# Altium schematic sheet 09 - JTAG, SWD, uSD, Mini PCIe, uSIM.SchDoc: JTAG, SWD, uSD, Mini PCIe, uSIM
size A3; PageSetup: Record=PageOptions¦CenterHorizontal=True¦CenterVertical=True¦PrintScale=0.70¦XCorrection=1.00¦YCorrection=1.00¦PrintKind=0¦BorderSize=5000000¦LeftOffset=0¦BottomOffset=0¦Orientation=2¦PaperLength=4200¦PaperWidth=2970¦Scale=100¦PaperSource=7¦PrintQuality=600¦MediaType=1¦DitherType=10¦PaperKind=A4¦PrintScaleMode=1; Author: Juan Anzola; SheetNumber: 9; SheetTotal: 21
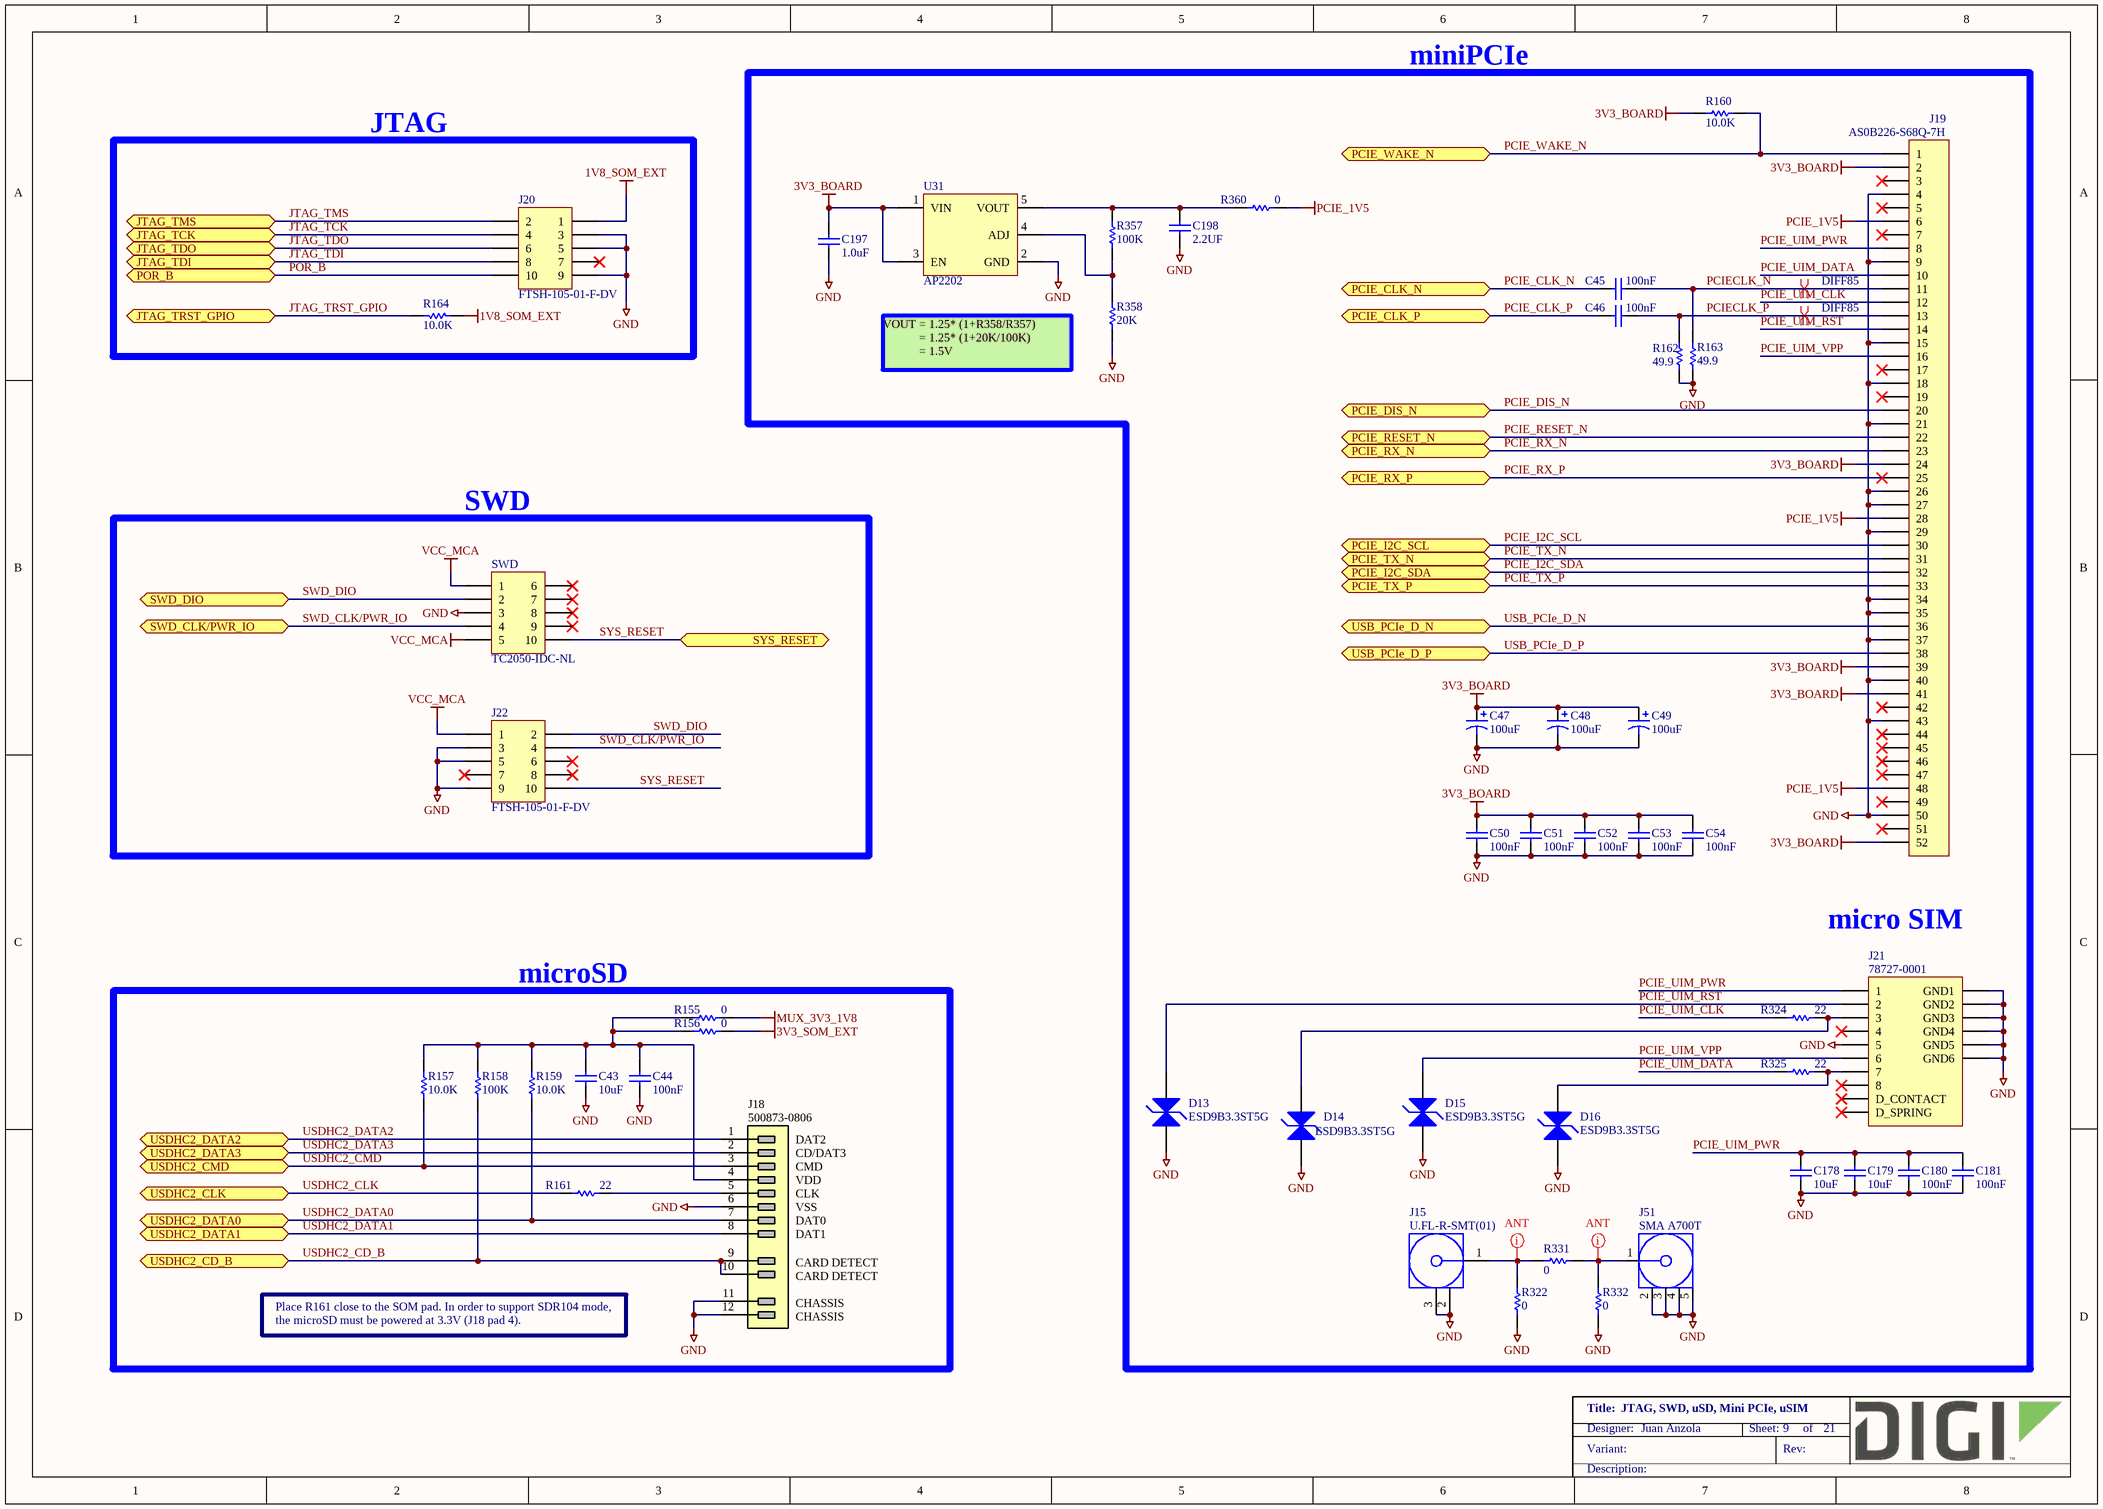
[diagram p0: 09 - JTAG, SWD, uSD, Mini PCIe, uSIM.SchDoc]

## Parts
C43  10uF  [CAPC1005X55N]
C44  100nF  [CAPC1005X55N]
C45  100nF  [CAPC1005X55N]
C46  100nF  [CAPC1005X55N]
C47  100uF  [CAPMP3216X120N]
C48  100uF  [CAPMP3216X120N]
C49  100uF  [CAPMP3216X120N]
C50  100nF  [CAPC1005X55N]
C51  100nF  [CAPC1005X55N]
C52  100nF  [CAPC1005X55N]
C53  100nF  [CAPC1005X55N]
C54  100nF  [CAPC1005X55N]
C178  10uF  [CAPC2013X135N]
C179  10uF  [CAPC2013X135N]
C180  100nF  [CAPC1005X55N]
C181  100nF  [CAPC1005X55N]
C197  1.0uF  [CAPC1005X55N]
C198  2.2UF  [CAPC1608X90N]
D13  ESD9B3.3ST5G  [SODFL1006X43AN12]
D14  ESD9B3.3ST5G  [SODFL1006X43AN12]
D15  ESD9B3.3ST5G  [SODFL1006X43AN12]
D16  ESD9B3.3ST5G  [SODFL1006X43AN12]
J15  U.FL-R-SMT(01)  [HIROSE_U.FL-R-SMT(01)]
J18  500873-0806  [MOLEX_500873-0806]
J19  Manufacturer_Part_Number: AS0B226-S68Q-7H  [FOXCONN_AS0B221-S68Q-7H]  (hidden comment: PCIe Minicard)
J20  FTSH-105-01-F-DV  [SAMTEC_FTSH-105-01-F-DV]
J21  78727-0001  [MOLEX_78727-0001]
J22  FTSH-105-01-F-DV  [SAMTEC_FTSH-105-01-F-DV]
J51  SMA A700T  [BOBBINTRON_SMA A700T]
R155  0  [RESC1005X40N]
R156  0  [RESC1005X40N]
R157  10.0K  [RESC1005X40N]
R158  100K  [RESC1005X40N]
R159  10.0K  [RESC1005X40N]
R160  10.0K  [RESC1005X40N]
R161  22  [RESC1005X40N]
R162  49.9  [RESC1005X40N]
R163  49.9  [RESC1005X40N]
R164  10.0K  [RESC1005X40N]
R322  0  [RESC1005X40N]
R324  22  [RESC1005X40N]
R325  22  [RESC1005X40N]
R331  0  [RESC1005X40N]
R332  0  [RESC1005X40N]
R357  100K  [RESC1005X40N]
R358  20K  [RESC1609X55N]
R360  0  [RESC1005X40N]
SWD  TC2050-IDC-NL  [TC_TC2050-IDC-NL]  (no BOM)
U31  AP2202  [SOT95P280X145-5N]

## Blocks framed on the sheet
JTAG: J20 R164
SWD: J22 SWD
microSD: C43 C44 J18 R155-R159 R161

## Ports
JTAG_TCK (bidir), JTAG_TDI (bidir), JTAG_TDO (bidir), JTAG_TMS (bidir), JTAG_TRST_GPIO (bidir), PCIE_CLK_N (bidir), PCIE_CLK_P (bidir), PCIE_DIS_N (bidir), PCIE_I2C_SCL (bidir), PCIE_I2C_SDA (bidir), PCIE_RESET_N (bidir), PCIE_RX_N (bidir), PCIE_RX_P (bidir), PCIE_TX_N (bidir), PCIE_TX_P (bidir), PCIE_WAKE_N (bidir), POR_B (bidir), SWD_CLK/PWR_IO (bidir), SWD_DIO (bidir), SYS_RESET (bidir), USB_PCIe_D_N (bidir), USB_PCIe_D_P (bidir), USDHC2_CD_B (bidir), USDHC2_CLK (bidir), USDHC2_CMD (bidir), USDHC2_DATA0 (bidir), USDHC2_DATA1 (bidir), USDHC2_DATA2 (bidir), USDHC2_DATA3 (bidir)

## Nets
1V8_SOM_EXT: J20.1 R164.1
3V3_BOARD: C47.1 C48.1 C49.1 C50.2 C51.2 C52.2 C53.2 C54.2 C197.1 J19.2 J19.24 J19.39 J19.41 J19.52 R160.2 U31.1(VIN) U31.3(EN)
3V3_SOM_EXT: R156.2
GND: C43.1 C44.1 C47.2 C48.2 C49.2 C50.1 C51.1 C52.1 C53.1 C54.1 C178.1 C179.1 C180.1 C181.1 C197.2 C198.1 D13.1 D14.1 D15.1 D16.1 J15.2(GND) J15.3(GND) J18.6 J18.11 J18.12 J19.4 J19.9 J19.15 J19.18 J19.21 J19.26 J19.27 J19.29 J19.34 J19.35 J19.37 J19.40 J19.43 J19.50 J20.3 J20.5 J20.9 J21.5 J21.11(GND1) J21.12(GND2) J21.13(GND3) J21.14(GND4) J21.15(GND5) J21.16(GND6) J22.3 J22.5 J22.9 J51.2(GND) J51.3(GND) J51.4(GND) J51.5(GND) R162.1 R163.1 R322.1 R332.1 R358.1 SWD.3 U31.2(GND)
MUX_3V3_1V8: R155.2
PCIE_1V5: J19.6 J19.28 J19.48 R360.2
VCC_MCA: J22.1 SWD.1 SWD.5
JTAG_TCK: J20.4 ; port JTAG_TCK
JTAG_TDI: J20.8 ; port JTAG_TDI
JTAG_TDO: J20.6 ; port JTAG_TDO
JTAG_TMS: J20.2 ; port JTAG_TMS
JTAG_TRST_GPIO: R164.2 ; port JTAG_TRST_GPIO
PCIE_CLK_N: C45.1 ; port PCIE_CLK_N
PCIE_CLK_P: C46.1 ; port PCIE_CLK_P
PCIE_DIS_N: J19.20 ; port PCIE_DIS_N
PCIE_I2C_SCL: J19.30 ; port PCIE_I2C_SCL
PCIE_I2C_SDA: J19.32 ; port PCIE_I2C_SDA
PCIE_RESET_N: J19.22 ; port PCIE_RESET_N
PCIE_RX_N: J19.23 ; port PCIE_RX_N
PCIE_RX_P: J19.25 ; port PCIE_RX_P
PCIE_TX_N: J19.31 ; port PCIE_TX_N
PCIE_TX_P: J19.33 ; port PCIE_TX_P
PCIE_UIM_CLK: J19.12 R324.1
PCIE_UIM_DATA: J19.10 R325.1
PCIE_UIM_PWR: C178.2 C179.2 C180.2 C181.2 J19.8 J21.1
PCIE_UIM_RST: D13.2 J19.14 J21.2
PCIE_UIM_VPP: D15.2 J19.16 J21.6
PCIE_WAKE_N: J19.1 R160.1 ; port PCIE_WAKE_N
PCIECLK_N: C45.2 J19.11 R163.2
PCIECLK_P: C46.2 J19.13 R162.2
POR_B: J20.10 ; port POR_B
SWD_CLK/PWR_IO: J22.4 SWD.4 ; port SWD_CLK/PWR_IO
SWD_DIO: J22.2 SWD.2 ; port SWD_DIO
SYS_RESET: J22.10 SWD.10 ; port SYS_RESET
USB_PCIe_D_N: J19.36 ; port USB_PCIe_D_N
USB_PCIe_D_P: J19.38 ; port USB_PCIe_D_P
USDHC2_CD_B: J18.9 J18.10 R158.2 ; port USDHC2_CD_B
USDHC2_CLK: R161.1 ; port USDHC2_CLK
USDHC2_CMD: J18.3 R157.1 ; port USDHC2_CMD
USDHC2_DATA0: J18.7 R159.1 ; port USDHC2_DATA0
USDHC2_DATA1: J18.8 ; port USDHC2_DATA1
USDHC2_DATA2: J18.1 ; port USDHC2_DATA2
USDHC2_DATA3: J18.2 ; port USDHC2_DATA3
NetC43_2: C43.2 C44.2 J18.4 R155.1 R156.1 R157.2 R158.1 R159.2
NetC198_2: C198.2 R357.2 R360.1 U31.5(VOUT)
NetD14_2: D14.2 J21.3 R324.2
NetD16_2: D16.2 J21.7 R325.2
NetJ15_1: J15.1(Signal) R322.2 R331.1
NetJ18_5: J18.5 R161.2
NetJ51_1: J51.1(Signal) R331.2 R332.2
NetR357_1: R357.1 R358.2 U31.4(ADJ)

Not connected (* = marked no-connect by the designer): J19 3* 5* 7* 17* 19* 42* 44* 45* 46* 47* 49* 51*; J20 7*; J21 4* 8* 9(D_CONTACT)* 10(D_SPRING)*; J22 6* 7* 8*; SWD 6* 7* 8* 9*

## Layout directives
differential pair; net class DIFF85: PCIECLK_N, PCIECLK_P
net class ANT: NetJ15_1, NetJ51_1

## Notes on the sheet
- miniPCIe
- VOUT = 1.25* (1+R358/R357)
  = 1.25* (1+20K/100K)
  = 1.5V
- micro SIM
- Place R161 close to the SOM pad. In order to support SDR104 mode,
- the microSD must be powered at 3.3V (J18 pad 4).

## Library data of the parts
C43 = 1001168: CAP CER 10UF 10V 20% X5R 0402; Part_Type: Capacitor; Manufacturer: Samsung; Manufacturer_Part_Number: CL05A106MP5NUNC; Digi_PN: 14050689; Component_Life_Cycle_State: Reviewed; Area: 0.95; Project: CCWMX6_SBC board
C44 C50-C54 C180 C181 = 1000006: CAP 100nF 16V 10% X7R 0402; Part_Type: Capacitor; Manufacturer: Murata; Manufacturer_Part_Number: GRM155R71C104KA88D; Component_Life_Cycle_State: CAD Reviewed; Area: 0.95; Project: KITT; Tolerance: 10; Digi_PN: 14050552
C45 C46 = 1000006: CAP 100nF 16V 10% X7R 0402; Part_Type: Capacitor; Manufacturer: Murata; Manufacturer_Part_Number: GRM155R71C104KA88D; Digi_PN: 14050552; Component_Life_Cycle_State: CAD Reviewed; Area: 0,95; Project: KITT; Tolerance: 10
C47-C49 = 1001196: CAP TANT 100UF 6.3V 20% 1206; Part_Type: Capacitor; Manufacturer: Rohm; Manufacturer_Part_Number: TCTAL0J107M8R; Digi_PN: 14050490; Component_Life_Cycle_State: Reviewed; Area: 8.01; Project: CCWMX6_SBC board
C178 C179 = 1000111: CAP CER 10UF 16V 10% X5R 0805; Part_Type: Capacitor; Manufacturer: Murata; Manufacturer_Part_Number: GRM21BR61C106KE15L; Digi_PN: 14050701; Component_Life_Cycle_State: Proven; Area: 3.99; Project: Adjustable Foundation; Tolerance: 10
C197 = 1001167: CAP CER 1UF 10V 10% X5R 0402; Part_Type: Capacitor; Manufacturer: Murata; Manufacturer_Part_Number: GRM155R61A105KE15D; Digi_PN: 14050399; Component_Life_Cycle_State: Reviewed; Area: 0,95
C198 = 1001303: CAP CER 2.2UF 16V 10% X5R 0603; Part_Type: Capacitor; Manufacturer: TDK Corporation; Manufacturer_Part_Number: C1608X5R1C225K080AB; Digi_PN: 14050730; Component_Life_Cycle_State: Reviewed; Area: 2,27
D13-D16 = 1001637: TVS DIODE 3.3VWM SOD923; Part_Type: Diodes; Manufacturer: On Semiconductor; Digi_PN: 17050883; Component_Life_Cycle_State: Reviewed; Area: 1,01
J15 = 1000027: RF Connectors U.FL RECEPTACLE SMT GLD M CONTACT; Manufacturer: Hirose; Digi_PN: 18000684; Component_Life_Cycle_State: Proven; Area: 14,4
J18 = 1001118: CONN TRANSFLSH R/A PUSH-PUSH SMD; Part_Type: Connector; Manufacturer: Molex; Digi_PN: MB03015; Component_Life_Cycle_State: Reviewed; Area: 213; Project: CCWMX6_SBC board
J19 = 1001130: SMCONN,MINI PCI EXP, 6.8MM HT; Part_Type: Connector; Manufacturer: Foxconn; Digi_PN: 18000349; Component_Life_Cycle_State: Reviewed; Area: 150; Project: CCWMX6_SBC board
J20 = 1000034: CONN HEADER 10POS DUAL .05" SMD; Part_Type: Connector; Manufacturer: Samtec; Note: 18000715 = Digi No. for GE WDNU; Digi_PN: 18000539; Component_Life_Cycle_State: Proven; Area: 43.55; Project: Adjustable Foundation
J21 = 1001120: MEMORY CARD 6POS PUSH/PULL SMD; Part_Type: Connector; Manufacturer: Molex; Digi_PN: 18000638; Component_Life_Cycle_State: Reviewed; Area: 217; Project: CCWMX6_SBC board
J22 = 1000034: CONN HEADER 10POS DUAL .05" SMD; Part_Type: Connector; Manufacturer: Samtec; Note: 18000715 = Digi No. for GE WDNU; Digi_PN: 18000539; Component_Life_Cycle_State: Proven; Area: 43,55; Project: Adjustable Foundation
J51 = 1002720: CONN SMA JACK R/A 50 OHM L15.1MM PCB TH; Part_Type: Connector; Manufacturer: Bobbintron Electrical Corp; Digi_PN: MA02979; Component_Life_Cycle_State: Reviewed; Area: 121,68
R155 R156 = 1000076: RES 0.0 OHM 1/10W 0402 SMD; Part_Type: Resistor; Manufacturer: Panasonic - ECG; Manufacturer_Part_Number: ERJ-2GE0R00X; Component_Life_Cycle_State: Proven; Area: 0.95; Project: Adjustable Foundation; Power_WV_SRF: 10; Digi_PN: 13050387
R157 R159 R160 R164 = 1000537: RES 10.0K OHM 1/10W 1% 0402 SMD; Part_Type: Resistor; Manufacturer: Panasonic - ECG; Manufacturer_Part_Number: ERJ-2RKF1002X; Component_Life_Cycle_State: CAD Reviewed; Area: 0.95; Project: KITT; Power_WV_SRF: 100; Digi_PN: 13051084
R158 = 1000480: RES 100K OHM 1/10W 1% 0402 SMD; Part_Type: Resistor; Manufacturer: Panasonic - ECG; Manufacturer_Part_Number: ERJ-2RKF1003X; Digi_PN: 13051063; Component_Life_Cycle_State: CAD Reviewed; Area: 0.95; Project: KITT; Power_WV_SRF: 100
R161 R324 R325 = 1000601: RES 22.0 OHM 1/10W 1% 0402 SMD; Part_Type: Resistor; Manufacturer: Panasonic - ECG; Manufacturer_Part_Number: ERJ-2RKF22R0X; Digi_PN: 13051089; Component_Life_Cycle_State: CAD Reviewed; Area: 0,95; Power_WV_SRF: 100
R162 R163 = 1000466: RES 49.9 OHM 1/10W 1% 0402 SMD; Part_Type: Resistor; Manufacturer: Panasonic - ECG; Manufacturer_Part_Number: ERJ-2RKF49R9X; Digi_PN: 13051083; Component_Life_Cycle_State: CAD Reviewed; Area: 0,95; Project: KITT; Power_WV_SRF: 100
R322 R331 R332 R360 = 1000076: RES 0.0 OHM 1/10W 0402 SMD; Part_Type: Resistor; Manufacturer: Panasonic - ECG; Manufacturer_Part_Number: ERJ-2GE0R00X; Digi_PN: 13050387; Component_Life_Cycle_State: Proven; Area: 0,95; Power_WV_SRF: 10
R357 = 1000480: RES 100K OHM 1/10W 1% 0402 SMD; Part_Type: Resistor; Manufacturer: Panasonic - ECG; Manufacturer_Part_Number: ERJ-2RKF1003X; Digi_PN: 13051063; Component_Life_Cycle_State: CAD Reviewed; Area: 0,95; Power_WV_SRF: 100
R358 = 1000142: RES 20K OHM 1/10W 5% 0603 SMD; Part_Type: Resistor; Manufacturer: Panasonic - ECG; Manufacturer_Part_Number: ERJ-3GEYJ203V; Digi_PN: 13050013; Component_Life_Cycle_State: Reviewed; Area: 2,5; Power_WV_SRF: 100; Tolerance: 5
SWD = CAD0066: CBL PLUG-OF-NAILS 10-PIN; Part_Type: Test Point; Component_Life_Cycle_State: Created; Area: 8; Project: CCWMX6_SBC board
U31 = 1001979: IC REG LDO ADJ 0.15A SOT25; Part_Type: Regulator; Manufacturer: Diodes, Inc.; Manufacturer_Part_Number: AP2202K-ADJTRG1; Digi_PN: 17050874; Component_Life_Cycle_State: Reviewed; Area: 14,92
